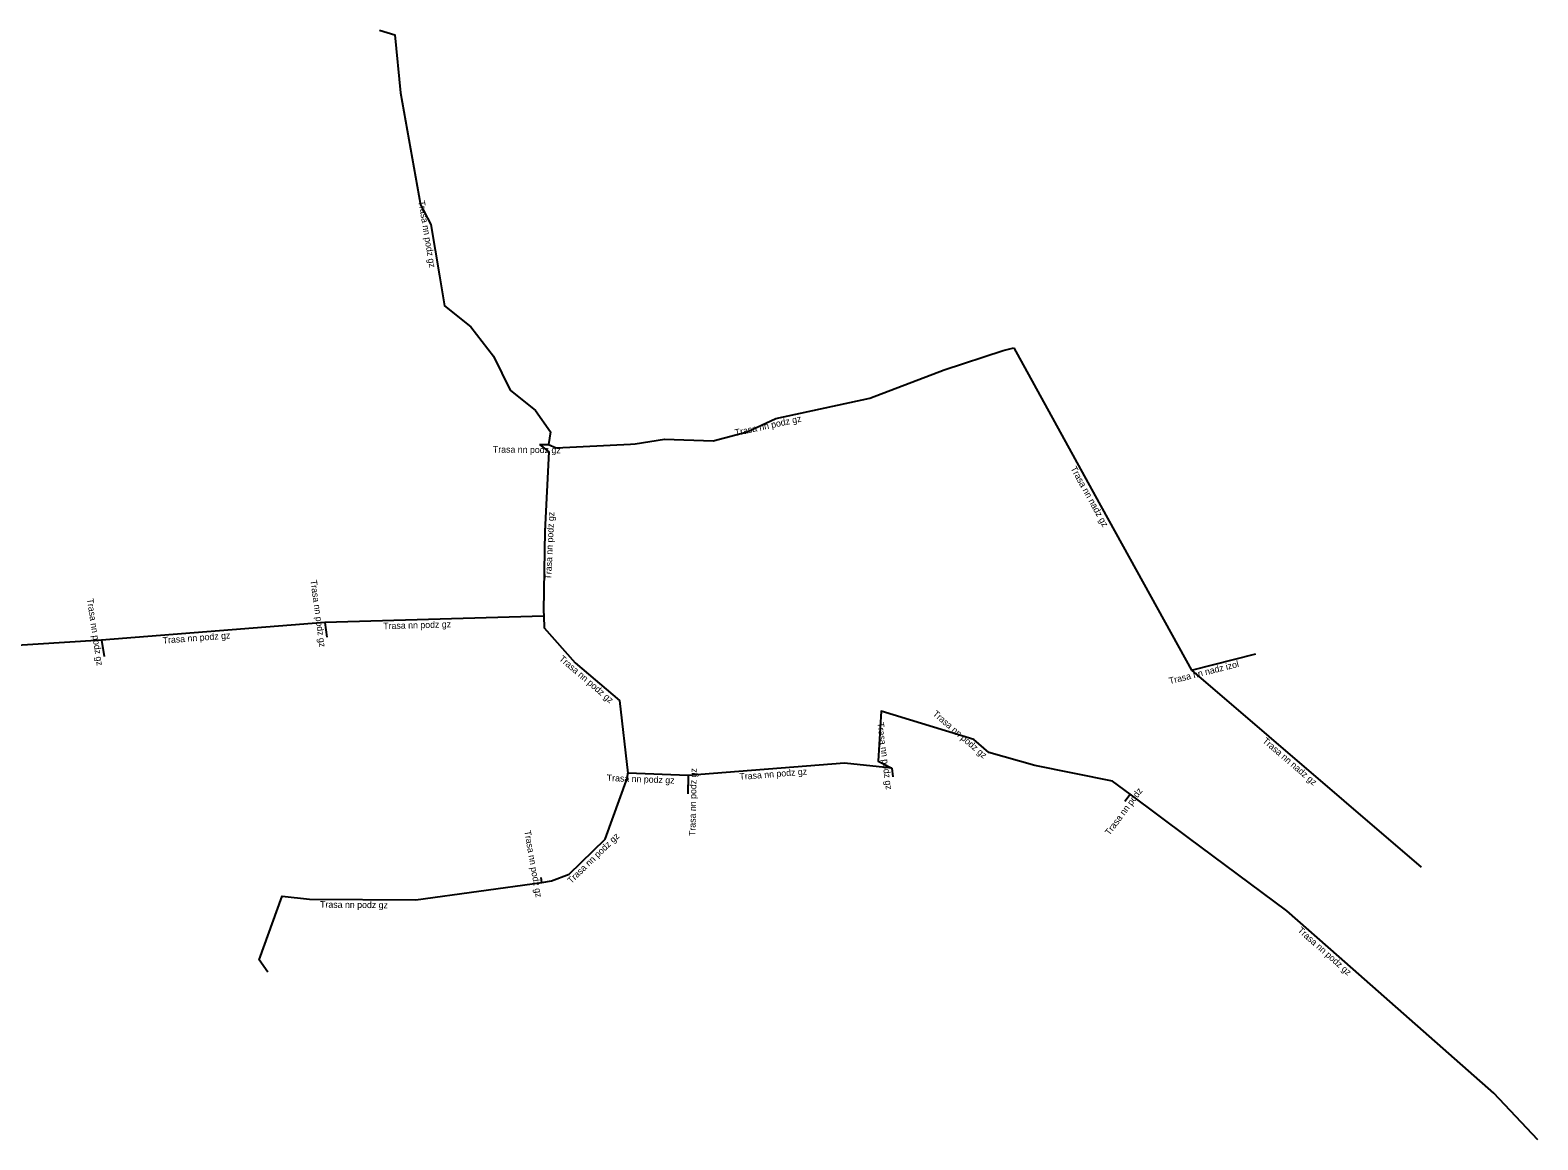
# Model space of a CAD drawing. Extents: x -778104 to -777779, y -1025034 to -1024901.
# Drawn here: x -777893.7 to -777778.9, y -1025033.5 to -1024949 of the extents above; entities that cross this region are included whole.
import ezdxf

# ---------------------------------------------------------------- set-up
doc = ezdxf.new("R2010")
doc.units = 0
doc.layers.add('Popiskový text - Ostatní atributy Trasy', color=7, linetype='Continuous')
doc.layers.add('Spojnice NN', color=7, linetype='Continuous')

msp = doc.modelspace()

# ---------------------------------------------------------------- linework, layer by layer
at = {"layer": 'Spojnice NN'}
for points in [[(-777867.12, -1024948.99), (-777865.94, -1024949.34), (-777865.51, -1024953.78), (-777863.98, -1024962.3), (-777863.2, -1024963.79), (-777862.55, -1024967.72), (-777862.17, -1024970), (-777860.16, -1024971.59), (-777858.43, -1024973.82), (-777857.16, -1024976.41), (-777855.24, -1024977.96), (-777854.1, -1024979.59), (-777854.24, -1024980.56)], [(-777854.24, -1024980.56), (-777853.65, -1024980.81), (-777848, -1024980.53), (-777847.64, -1024980.51), (-777845.41, -1024980.16), (-777841.7, -1024980.28), (-777839.12, -1024979.58), (-777836.92, -1024978.58), (-777829.77, -1024977.02), (-777824.1, -1024974.88), (-777819.61, -1024973.39), (-777818.8, -1024973.2)], [(-777818.8, -1024973.2), (-777812.6, -1024984.47), (-777805.27, -1024997.74)], [(-777854.92, -1024980.56), (-777854.24, -1024980.56)], [(-777854.92, -1024980.56), (-777854.22, -1024981.11), (-777854.51, -1024987.17), (-777854.62, -1024993.2), (-777854.61, -1024993.64)], [(-777871.28, -1024994.11), (-777888.28, -1024995.45)], [(-777854.61, -1024993.64), (-777871.28, -1024994.11)], [(-777871.28, -1024994.11), (-777871.13, -1024995.22)], [(-777854.61, -1024993.64), (-777854.57, -1024994.53), (-777852.21, -1024997.18), (-777848.84, -1025000.06), (-777848.19, -1025005.6)], [(-777888.28, -1024995.45), (-777901.6, -1024996.3), (-777908.25, -1024996.17)], [(-777888.28, -1024995.45), (-777888.09, -1024996.7)], [(-777805.27, -1024997.74), (-777800.37, -1024996.51)], [(-777805.27, -1024997.74), (-777787.78, -1025012.75)], [(-777809.95, -1025007.2), (-777811.28, -1025006.21), (-777817.21, -1025005.01), (-777820.7, -1025004.02), (-777821.85, -1025003.02), (-777828.91, -1025000.88), (-777829.12, -1025004.67), (-777828.09, -1025005.2)], [(-777854.75, -1025013.91), (-777854.02, -1025013.79), (-777852.67, -1025013.29), (-777849.93, -1025010.63), (-777848.23, -1025005.93), (-777848.19, -1025005.6)], [(-777843.61, -1025005.77), (-777848.19, -1025005.6)], [(-777828.09, -1025005.2), (-777831.69, -1025004.82), (-777843.61, -1025005.77)], [(-777828.09, -1025005.2), (-777828.01, -1025005.86)], [(-777843.61, -1025005.77), (-777843.64, -1025007.17)], [(-777810.34, -1025007.72), (-777809.95, -1025007.2)], [(-777778.89, -1025033.52), (-777782.24, -1025029.97), (-777794.03, -1025019.59), (-777798.01, -1025016.07), (-777805.53, -1025010.49), (-777809.95, -1025007.2)], [(-777854.75, -1025013.91), (-777854.81, -1025013.54)], [(-777875.62, -1025020.75), (-777876.27, -1025019.81), (-777874.52, -1025014.97), (-777872.44, -1025015.19), (-777864.34, -1025015.25), (-777854.75, -1025013.91)]]:
    msp.add_lwpolyline(points, dxfattribs=at)

# ---------------------------------------------------------------- texts
at = {"layer": 'Popiskový text - Ostatní atributy Trasy'}
for s, rotation, p in [('Trasa nn podz gz', 279.486, (-777864.16, -1024962.02)), ('Trasa nn podz gz', 12.3333, (-777839.99, -1024979.91)), ('Trasa nn podz gz', 359.4093, (-777858.48, -1024981.17)), ('Trasa nn nadz gz', 298.9338, (-777814.5, -1024982.38)), ('Trasa nn podz gz', 87.3254, (-777854.03, -1024990.85)), ('Trasa nn podz gz', 277.7974, (-777872.38, -1024990.9)), ('Trasa nn podz gz', 278.4749, (-777889.4, -1024992.32)), ('Trasa nn podz gz', 1.6184, (-777866.82, -1024994.63)), ('Trasa nn podz gz', 4.4912, (-777883.61, -1024995.73)), ('Trasa nn podz gz', 319.4841, (-777853.48, -1024996.95)), ('Trasa nn nadz izol', 14.0748, (-777806.92, -1024998.82)), ('Trasa nn podz gz', 319.2315, (-777825.02, -1025001.14)), ('Trasa nn podz gz', 277.4018, (-777829.2, -1025001.75)), ('Trasa nn nadz gz', 319.3626, (-777799.9, -1025003.2)), ('Trasa nn podz gz', 357.8484, (-777849.81, -1025006.19)), ('Trasa nn podz gz', 88.8959, (-777843.05, -1025010.38)), ('Trasa nn podz gz', 4.5711, (-777839.68, -1025006.11)), ('Trasa nn podz', 53.3844, (-777811.51, -1025010.37)), ('Trasa nn podz gz', 279.8922, (-777856.09, -1025010)), ('Trasa nn podz gz', 44.0994, (-777852.51, -1025014.04)), ('Trasa nn podz gz', 359.5474, (-777871.64, -1025015.84)), ('Trasa nn podz gz', 318.6318, (-777797.23, -1025017.63))]:
    msp.add_text(s, height=0.5, rotation=rotation, dxfattribs=at).set_placement(p)

doc.saveas('drawing.dxf')
